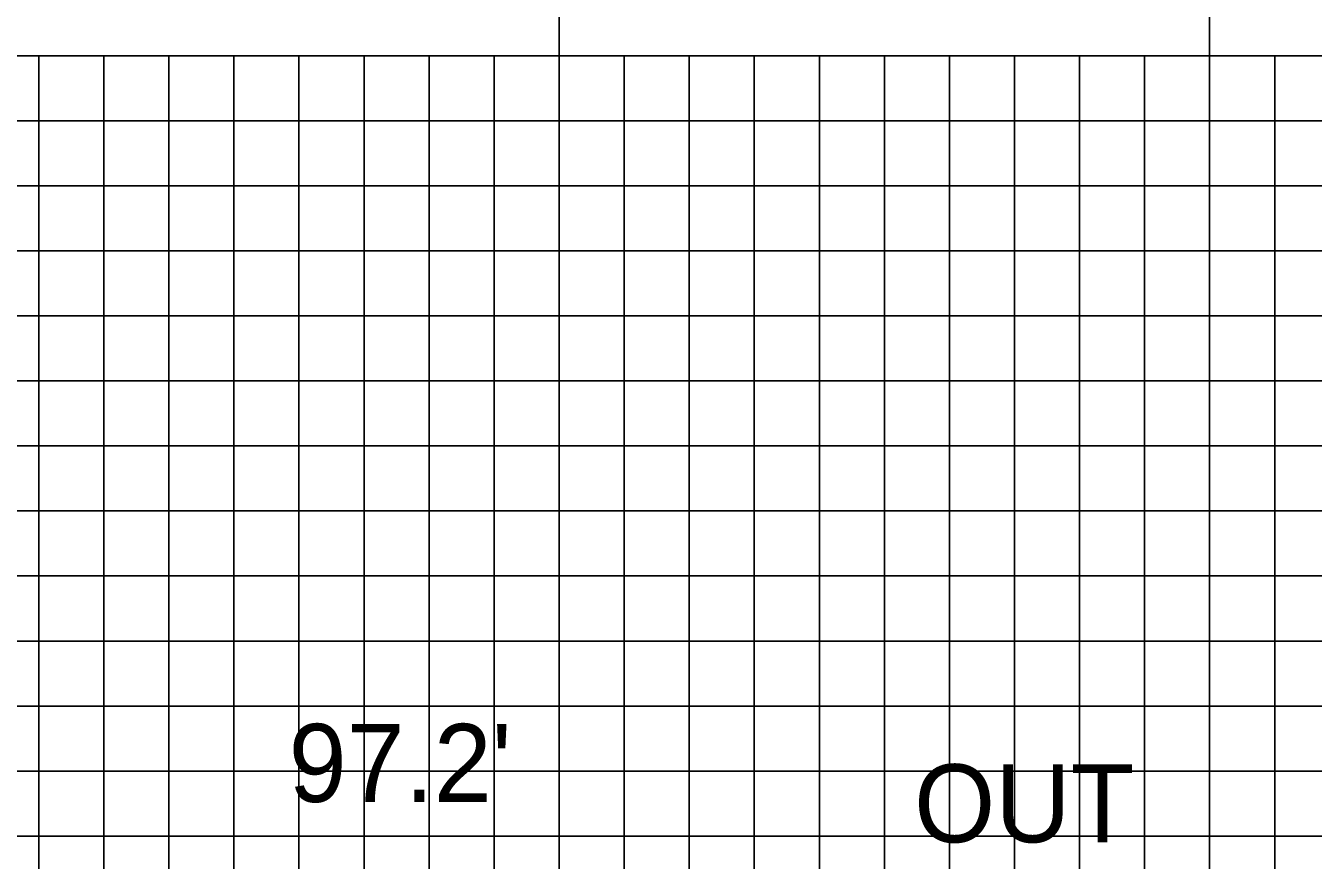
# Model space of a CAD drawing. Extents: x 1763365 to 1763708, y 442591 to 442811.
# Drawn here: x 1763422.6 to 1763442.4, y 442726.29 to 442739.13 of the extents above; entities that cross this region are included whole.
import ezdxf

# ---------------------------------------------------------------- set-up
doc = ezdxf.new("R2010")
doc.units = 0
for name, color, linetype in [('ANNOTATION', 7, 'Continuous'), ('D_Text_Standard', 7, 'Continuous'), ('MAJOR', 7, 'Continuous'), ('MINOR', 7, 'Continuous')]:
    doc.layers.add(name, color=color, linetype=linetype)

msp = doc.modelspace()

# ---------------------------------------------------------------- linework, layer by layer
at = {"layer": 'MAJOR'}
for p, q in [((1763430.805, 442740.669), (1763430.805, 442738.665)), ((1763440.805, 442740.669), (1763440.805, 442738.665)), ((1763390.805, 442738.665), (1763670.805, 442738.665)), ((1763390.805, 442738.665), (1763670.805, 442738.665)), ((1763430.805, 442713.665), (1763430.805, 442738.665)), ((1763440.805, 442713.665), (1763440.805, 442738.665)), ((1763390.805, 442733.665), (1763670.805, 442733.665)), ((1763390.805, 442728.665), (1763670.805, 442728.665))]:
    msp.add_line(p, q, dxfattribs=at)
at = {"layer": 'MINOR'}
for p, q in [((1763422.805, 442713.665), (1763422.805, 442738.665)), ((1763423.805, 442713.665), (1763423.805, 442738.665)), ((1763424.805, 442713.665), (1763424.805, 442738.665)), ((1763425.805, 442713.665), (1763425.805, 442738.665)), ((1763426.805, 442713.665), (1763426.805, 442738.665)), ((1763427.805, 442713.665), (1763427.805, 442738.665)), ((1763428.805, 442713.665), (1763428.805, 442738.665)), ((1763429.805, 442713.665), (1763429.805, 442738.665)), ((1763431.805, 442713.665), (1763431.805, 442738.665)), ((1763432.805, 442713.665), (1763432.805, 442738.665)), ((1763433.805, 442713.665), (1763433.805, 442738.665)), ((1763434.805, 442713.665), (1763434.805, 442738.665)), ((1763435.805, 442713.665), (1763435.805, 442738.665)), ((1763436.805, 442713.665), (1763436.805, 442738.665)), ((1763437.805, 442713.665), (1763437.805, 442738.665)), ((1763438.805, 442713.665), (1763438.805, 442738.665)), ((1763439.805, 442713.665), (1763439.805, 442738.665)), ((1763441.805, 442713.665), (1763441.805, 442738.665)), ((1763390.805, 442737.665), (1763670.805, 442737.665)), ((1763390.805, 442736.665), (1763670.805, 442736.665)), ((1763390.805, 442735.665), (1763670.805, 442735.665)), ((1763390.805, 442734.665), (1763670.805, 442734.665)), ((1763390.805, 442732.665), (1763670.805, 442732.665)), ((1763390.805, 442731.665), (1763670.805, 442731.665)), ((1763390.805, 442730.665), (1763670.805, 442730.665)), ((1763390.805, 442729.665), (1763670.805, 442729.665)), ((1763390.805, 442727.665), (1763670.805, 442727.665)), ((1763390.805, 442726.665), (1763670.805, 442726.665))]:
    msp.add_line(p, q, dxfattribs=at)

# ---------------------------------------------------------------- texts
at = {"layer": 'ANNOTATION'}
msp.add_text('OUT', height=1.2, dxfattribs=at).set_placement((1763436.261, 442726.569))
at = {"layer": 'D_Text_Standard'}
msp.add_text("97.2'", height=1.2, dxfattribs=at).set_placement((1763426.646, 442727.19))

doc.saveas('drawing.dxf')
